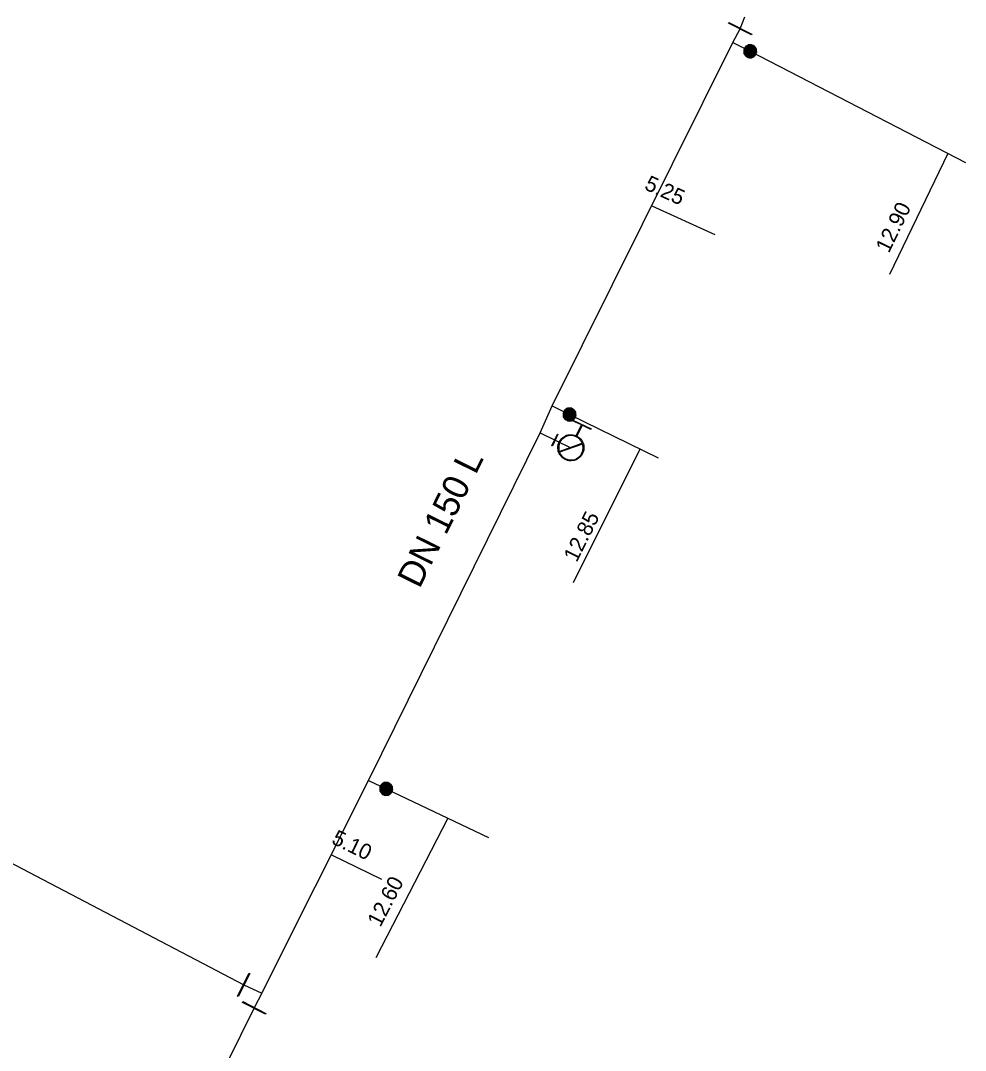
# Model space of a CAD drawing. Extents: x -820257 to -819974, y -1070894 to -1070484.
# Drawn here: x -820109.2 to -820036.2, y -1070745.2 to -1070665.6 of the extents above; entities that cross this region are included whole.
import ezdxf

# ---------------------------------------------------------------- set-up
doc = ezdxf.new("R2010")
doc.units = 0
for name, color, linetype in [('Hyd-odbočka', 7, 'Continuous'), ('Hyd-šoupě', 7, 'Continuous'), ('Hydrant', 7, 'Continuous'), ('Oměrka vodovodu', 7, 'Continuous'), ('Oměrka-text', 7, 'Continuous'), ('Přípojka vodovodu', 7, 'Continuous'), ('Přípojkový uzávěr', 7, 'Continuous'), ('Roz-řad', 7, 'Continuous'), ('Roz-řad-popis základní', 7, 'Continuous'), ('Řad-šoupě', 7, 'Continuous')]:
    doc.layers.add(name, color=color, linetype=linetype)

msp = doc.modelspace()

# ---------------------------------------------------------------- linework, layer by layer
at = {"layer": 'Hyd-odbočka'}
msp.add_line((-820069.077, -1070697.474), (-820066.695, -1070698.626), dxfattribs=at)
at = {"layer": 'Hyd-šoupě'}
msp.add_lwpolyline([(-820067.693, -1070697.588), (-820068.128, -1070698.488), (-820068.156, -1070698.474), (-820067.721, -1070697.574), (-820067.693, -1070697.588)], dxfattribs=at)
at = {"layer": 'Hydrant'}
for points in [[(-820066.29, -1070697.711), (-820065.885, -1070696.866), (-820066.561, -1070696.541), (-820066.534, -1070696.485), (-820065.125, -1070697.161), (-820065.152, -1070697.218), (-820065.828, -1070696.893), (-820066.234, -1070697.738)], [(-820067.591, -1070698.909), (-820065.819, -1070698.286)], [(-820065.799, -1070698.344), (-820067.572, -1070698.968)]]:
    msp.add_lwpolyline(points, dxfattribs=at)
for points in [[(-820066.234, -1070697.738), (-820066.024, -1070697.847), (-820065.874, -1070698.054), (-820065.715, -1070698.273), (-820065.698, -1070698.548), (-820065.68, -1070698.823), (-820065.793, -1070699.059), (-820065.906, -1070699.293), (-820066.128, -1070699.451), (-820066.35, -1070699.609), (-820066.622, -1070699.624), (-820066.893, -1070699.64), (-820067.128, -1070699.528), (-820067.362, -1070699.415), (-820067.52, -1070699.193), (-820067.677, -1070698.971), (-820067.693, -1070698.699), (-820067.709, -1070698.428), (-820067.596, -1070698.193), (-820067.483, -1070697.957), (-820067.258, -1070697.799), (-820067.032, -1070697.641), (-820066.762, -1070697.628), (-820066.508, -1070697.615), (-820066.29, -1070697.711)], [(-820065.819, -1070698.286), (-820065.86, -1070698.182), (-820065.926, -1070698.09), (-820066.076, -1070697.883), (-820066.289, -1070697.781), (-820066.502, -1070697.679), (-820066.757, -1070697.691), (-820067.012, -1070697.703), (-820067.223, -1070697.851), (-820067.434, -1070697.999), (-820067.54, -1070698.22), (-820067.646, -1070698.44), (-820067.629, -1070698.695), (-820067.624, -1070698.806), (-820067.591, -1070698.909)], [(-820067.572, -1070698.968), (-820067.533, -1070699.067), (-820067.467, -1070699.157), (-820067.321, -1070699.366), (-820067.101, -1070699.471), (-820066.881, -1070699.577), (-820066.625, -1070699.562), (-820066.37, -1070699.547), (-820066.163, -1070699.399), (-820065.955, -1070699.252), (-820065.85, -1070699.032), (-820065.743, -1070698.81), (-820065.76, -1070698.553), (-820065.768, -1070698.443), (-820065.799, -1070698.344)]]:
    msp.add_open_spline(points, degree=3, dxfattribs=at)
at = {"layer": 'Oměrka vodovodu'}
for p, q in [((-820037.577, -1070675.914), (-820042.09, -1070685.243)), ((-820060.456, -1070679.934), (-820055.57, -1070682.157)), ((-820061.365, -1070698.725), (-820066.528, -1070709.053)), ((-820076.192, -1070727.239), (-820081.747, -1070738.009)), ((-820085.19, -1070730.062), (-820081.33, -1070731.931))]:
    msp.add_line(p, q, dxfattribs=at)
at = {"layer": 'Přípojka vodovodu'}
for points in [[(-820054.182, -1070667.321), (-820052.85, -1070668.01), (-820036.232, -1070676.61)], [(-820068.149, -1070695.401), (-820066.802, -1070696.061), (-820059.956, -1070699.415)], [(-820082.313, -1070724.324), (-820080.959, -1070724.969), (-820073.047, -1070728.737)]]:
    msp.add_lwpolyline(points, dxfattribs=at)
at = {"layer": 'Přípojkový uzávěr'}
for points in [[(-820052.621, -1070667.565), (-820052.509, -1070667.623), (-820052.432, -1070667.736), (-820052.356, -1070667.848), (-820052.351, -1070667.986), (-820052.346, -1070668.124), (-820052.406, -1070668.24), (-820052.466, -1070668.355), (-820052.579, -1070668.431), (-820052.692, -1070668.506), (-820052.828, -1070668.51), (-820052.965, -1070668.513), (-820053.08, -1070668.454), (-820053.195, -1070668.394), (-820053.271, -1070668.281), (-820053.346, -1070668.168), (-820053.35, -1070668.032), (-820053.354, -1070667.896), (-820053.294, -1070667.78), (-820053.234, -1070667.664), (-820053.119, -1070667.588), (-820053.004, -1070667.512), (-820052.869, -1070667.51), (-820052.733, -1070667.507), (-820052.621, -1070667.565)], [(-820052.642, -1070667.607), (-820052.744, -1070667.555), (-820052.867, -1070667.557), (-820052.99, -1070667.559), (-820053.094, -1070667.628), (-820053.198, -1070667.697), (-820053.253, -1070667.802), (-820053.307, -1070667.906), (-820053.303, -1070668.029), (-820053.3, -1070668.152), (-820053.231, -1070668.255), (-820053.163, -1070668.358), (-820053.059, -1070668.412), (-820052.954, -1070668.466), (-820052.83, -1070668.463), (-820052.707, -1070668.459), (-820052.604, -1070668.391), (-820052.502, -1070668.323), (-820052.448, -1070668.218), (-820052.393, -1070668.113), (-820052.398, -1070667.988), (-820052.402, -1070667.863), (-820052.472, -1070667.761), (-820052.541, -1070667.66), (-820052.642, -1070667.607)], [(-820052.658, -1070667.637), (-820052.564, -1070667.686), (-820052.5, -1070667.78), (-820052.436, -1070667.874), (-820052.432, -1070667.989), (-820052.428, -1070668.105), (-820052.478, -1070668.203), (-820052.528, -1070668.299), (-820052.623, -1070668.363), (-820052.717, -1070668.426), (-820052.832, -1070668.429), (-820052.946, -1070668.432), (-820053.043, -1070668.382), (-820053.139, -1070668.332), (-820053.203, -1070668.237), (-820053.266, -1070668.142), (-820053.269, -1070668.028), (-820053.272, -1070667.914), (-820053.222, -1070667.818), (-820053.172, -1070667.72), (-820053.076, -1070667.656), (-820052.98, -1070667.593), (-820052.866, -1070667.591), (-820052.752, -1070667.589), (-820052.658, -1070667.637)], [(-820052.679, -1070667.676), (-820052.817, -1070667.604), (-820052.965, -1070667.652), (-820053.112, -1070667.699), (-820053.183, -1070667.838), (-820053.255, -1070667.976), (-820053.208, -1070668.124), (-820053.16, -1070668.271), (-820053.023, -1070668.342), (-820052.885, -1070668.414), (-820052.737, -1070668.367), (-820052.589, -1070668.32), (-820052.517, -1070668.183), (-820052.446, -1070668.044), (-820052.492, -1070667.896), (-820052.539, -1070667.749), (-820052.679, -1070667.676)], [(-820052.7, -1070667.717), (-820052.578, -1070667.78), (-820052.537, -1070667.909), (-820052.497, -1070668.038), (-820052.559, -1070668.159), (-820052.622, -1070668.28), (-820052.751, -1070668.321), (-820052.88, -1070668.362), (-820053.001, -1070668.3), (-820053.123, -1070668.237), (-820053.164, -1070668.108), (-820053.205, -1070667.979), (-820053.142, -1070667.858), (-820053.079, -1070667.737), (-820052.95, -1070667.695), (-820052.821, -1070667.654), (-820052.7, -1070667.717)], [(-820052.718, -1070667.752), (-820052.825, -1070667.697), (-820052.938, -1070667.733), (-820053.052, -1070667.77), (-820053.107, -1070667.876), (-820053.162, -1070667.982), (-820053.126, -1070668.096), (-820053.09, -1070668.21), (-820052.983, -1070668.265), (-820052.877, -1070668.32), (-820052.763, -1070668.283), (-820052.649, -1070668.247), (-820052.594, -1070668.141), (-820052.539, -1070668.035), (-820052.575, -1070667.921), (-820052.611, -1070667.808), (-820052.718, -1070667.752)], [(-820052.736, -1070667.787), (-820052.642, -1070667.836), (-820052.611, -1070667.934), (-820052.581, -1070668.033), (-820052.628, -1070668.125), (-820052.676, -1070668.217), (-820052.775, -1070668.248), (-820052.873, -1070668.279), (-820052.965, -1070668.232), (-820053.057, -1070668.184), (-820053.088, -1070668.086), (-820053.12, -1070667.987), (-820053.072, -1070667.895), (-820053.025, -1070667.803), (-820052.927, -1070667.771), (-820052.828, -1070667.739), (-820052.736, -1070667.787)], [(-820052.757, -1070667.829), (-820052.832, -1070667.79), (-820052.912, -1070667.815), (-820052.992, -1070667.841), (-820053.031, -1070667.916), (-820053.07, -1070667.991), (-820053.044, -1070668.071), (-820053.019, -1070668.151), (-820052.944, -1070668.189), (-820052.869, -1070668.228), (-820052.789, -1070668.203), (-820052.709, -1070668.177), (-820052.67, -1070668.102), (-820052.631, -1070668.027), (-820052.657, -1070667.947), (-820052.682, -1070667.868), (-820052.757, -1070667.829)], [(-820052.773, -1070667.859), (-820052.71, -1070667.892), (-820052.689, -1070667.958), (-820052.668, -1070668.024), (-820052.701, -1070668.087), (-820052.733, -1070668.149), (-820052.799, -1070668.17), (-820052.866, -1070668.191), (-820052.928, -1070668.159), (-820052.99, -1070668.126), (-820053.011, -1070668.06), (-820053.032, -1070667.994), (-820053, -1070667.932), (-820052.968, -1070667.869), (-820052.902, -1070667.848), (-820052.835, -1070667.827), (-820052.773, -1070667.859)], [(-820052.793, -1070667.898), (-820052.839, -1070667.875), (-820052.888, -1070667.891), (-820052.937, -1070667.906), (-820052.961, -1070667.952), (-820052.985, -1070667.998), (-820052.969, -1070668.048), (-820052.954, -1070668.097), (-820052.908, -1070668.121), (-820052.862, -1070668.145), (-820052.812, -1070668.129), (-820052.763, -1070668.113), (-820052.739, -1070668.067), (-820052.715, -1070668.021), (-820052.731, -1070667.972), (-820052.746, -1070667.923), (-820052.793, -1070667.898)], [(-820052.815, -1070667.94), (-820052.785, -1070667.955), (-820052.776, -1070667.986), (-820052.766, -1070668.016), (-820052.781, -1070668.045), (-820052.796, -1070668.074), (-820052.826, -1070668.084), (-820052.857, -1070668.094), (-820052.886, -1070668.079), (-820052.915, -1070668.064), (-820052.925, -1070668.033), (-820052.935, -1070668.002), (-820052.92, -1070667.974), (-820052.905, -1070667.944), (-820052.874, -1070667.935), (-820052.843, -1070667.925), (-820052.815, -1070667.94)], [(-820052.829, -1070667.968), (-820052.846, -1070667.959), (-820052.865, -1070667.965), (-820052.883, -1070667.97), (-820052.892, -1070667.988), (-820052.901, -1070668.005), (-820052.895, -1070668.024), (-820052.889, -1070668.042), (-820052.872, -1070668.051), (-820052.854, -1070668.06), (-820052.836, -1070668.054), (-820052.818, -1070668.048), (-820052.809, -1070668.031), (-820052.8, -1070668.013), (-820052.805, -1070667.995), (-820052.811, -1070667.977), (-820052.829, -1070667.968)], [(-820066.582, -1070695.612), (-820066.469, -1070695.667), (-820066.39, -1070695.778), (-820066.311, -1070695.888), (-820066.303, -1070696.026), (-820066.296, -1070696.164), (-820066.353, -1070696.281), (-820066.41, -1070696.398), (-820066.522, -1070696.476), (-820066.633, -1070696.554), (-820066.769, -1070696.56), (-820066.905, -1070696.567), (-820067.022, -1070696.51), (-820067.139, -1070696.453), (-820067.217, -1070696.341), (-820067.295, -1070696.23), (-820067.301, -1070696.094), (-820067.308, -1070695.958), (-820067.251, -1070695.841), (-820067.194, -1070695.724), (-820067.08, -1070695.645), (-820066.967, -1070695.567), (-820066.832, -1070695.561), (-820066.696, -1070695.556), (-820066.582, -1070695.612)], [(-820066.603, -1070695.654), (-820066.706, -1070695.604), (-820066.829, -1070695.608), (-820066.952, -1070695.613), (-820067.054, -1070695.684), (-820067.157, -1070695.756), (-820067.209, -1070695.862), (-820067.261, -1070695.968), (-820067.255, -1070696.091), (-820067.249, -1070696.214), (-820067.178, -1070696.315), (-820067.107, -1070696.416), (-820067.002, -1070696.468), (-820066.896, -1070696.52), (-820066.772, -1070696.514), (-820066.649, -1070696.507), (-820066.548, -1070696.437), (-820066.447, -1070696.366), (-820066.395, -1070696.261), (-820066.343, -1070696.154), (-820066.35, -1070696.029), (-820066.358, -1070695.904), (-820066.429, -1070695.804), (-820066.5, -1070695.704), (-820066.603, -1070695.654)], [(-820066.618, -1070695.685), (-820066.523, -1070695.731), (-820066.457, -1070695.824), (-820066.391, -1070695.916), (-820066.384, -1070696.032), (-820066.378, -1070696.147), (-820066.426, -1070696.246), (-820066.474, -1070696.344), (-820066.567, -1070696.409), (-820066.66, -1070696.474), (-820066.774, -1070696.48), (-820066.889, -1070696.485), (-820066.987, -1070696.437), (-820067.084, -1070696.389), (-820067.15, -1070696.296), (-820067.215, -1070696.202), (-820067.221, -1070696.088), (-820067.226, -1070695.975), (-820067.178, -1070695.877), (-820067.13, -1070695.778), (-820067.035, -1070695.713), (-820066.941, -1070695.647), (-820066.827, -1070695.642), (-820066.713, -1070695.638), (-820066.618, -1070695.685)], [(-820066.638, -1070695.724), (-820066.778, -1070695.655), (-820066.924, -1070695.706), (-820067.07, -1070695.757), (-820067.139, -1070695.896), (-820067.207, -1070696.036), (-820067.157, -1070696.183), (-820067.106, -1070696.329), (-820066.968, -1070696.397), (-820066.828, -1070696.466), (-820066.681, -1070696.416), (-820066.534, -1070696.366), (-820066.465, -1070696.226), (-820066.397, -1070696.087), (-820066.447, -1070695.94), (-820066.496, -1070695.793), (-820066.638, -1070695.724)], [(-820066.658, -1070695.765), (-820066.535, -1070695.825), (-820066.491, -1070695.954), (-820066.448, -1070696.082), (-820066.508, -1070696.204), (-820066.568, -1070696.326), (-820066.696, -1070696.37), (-820066.824, -1070696.414), (-820066.947, -1070696.354), (-820067.07, -1070696.294), (-820067.113, -1070696.166), (-820067.157, -1070696.038), (-820067.097, -1070695.915), (-820067.037, -1070695.793), (-820066.909, -1070695.749), (-820066.781, -1070695.705), (-820066.658, -1070695.765)], [(-820066.675, -1070695.801), (-820066.783, -1070695.748), (-820066.896, -1070695.786), (-820067.009, -1070695.825), (-820067.062, -1070695.933), (-820067.114, -1070696.04), (-820067.076, -1070696.153), (-820067.037, -1070696.266), (-820066.929, -1070696.319), (-820066.822, -1070696.371), (-820066.709, -1070696.333), (-820066.596, -1070696.294), (-820066.543, -1070696.187), (-820066.491, -1070696.079), (-820066.529, -1070695.966), (-820066.567, -1070695.854), (-820066.675, -1070695.801)], [(-820066.692, -1070695.836), (-820066.598, -1070695.882), (-820066.565, -1070695.98), (-820066.532, -1070696.078), (-820066.578, -1070696.171), (-820066.623, -1070696.264), (-820066.721, -1070696.298), (-820066.819, -1070696.331), (-820066.912, -1070696.285), (-820067.005, -1070696.24), (-820067.039, -1070696.142), (-820067.072, -1070696.044), (-820067.027, -1070695.951), (-820066.981, -1070695.858), (-820066.884, -1070695.824), (-820066.786, -1070695.79), (-820066.692, -1070695.836)], [(-820066.713, -1070695.878), (-820066.789, -1070695.841), (-820066.868, -1070695.868), (-820066.947, -1070695.895), (-820066.985, -1070695.971), (-820067.022, -1070696.047), (-820066.995, -1070696.126), (-820066.967, -1070696.206), (-820066.892, -1070696.243), (-820066.816, -1070696.28), (-820066.737, -1070696.253), (-820066.657, -1070696.226), (-820066.62, -1070696.15), (-820066.583, -1070696.074), (-820066.61, -1070695.994), (-820066.637, -1070695.915), (-820066.713, -1070695.878)], [(-820066.728, -1070695.909), (-820066.665, -1070695.94), (-820066.643, -1070696.006), (-820066.62, -1070696.071), (-820066.651, -1070696.134), (-820066.682, -1070696.198), (-820066.748, -1070696.22), (-820066.814, -1070696.242), (-820066.876, -1070696.212), (-820066.939, -1070696.181), (-820066.962, -1070696.115), (-820066.984, -1070696.049), (-820066.954, -1070695.986), (-820066.923, -1070695.923), (-820066.857, -1070695.901), (-820066.791, -1070695.878), (-820066.728, -1070695.909)], [(-820066.747, -1070695.949), (-820066.794, -1070695.926), (-820066.843, -1070695.943), (-820066.891, -1070695.96), (-820066.914, -1070696.006), (-820066.937, -1070696.052), (-820066.92, -1070696.101), (-820066.903, -1070696.15), (-820066.857, -1070696.173), (-820066.811, -1070696.196), (-820066.762, -1070696.179), (-820066.713, -1070696.162), (-820066.69, -1070696.116), (-820066.667, -1070696.069), (-820066.684, -1070696.021), (-820066.7, -1070695.972), (-820066.747, -1070695.949)], [(-820066.768, -1070695.991), (-820066.738, -1070696.005), (-820066.728, -1070696.035), (-820066.718, -1070696.065), (-820066.732, -1070696.095), (-820066.746, -1070696.124), (-820066.777, -1070696.135), (-820066.807, -1070696.146), (-820066.837, -1070696.131), (-820066.866, -1070696.117), (-820066.876, -1070696.086), (-820066.887, -1070696.055), (-820066.873, -1070696.026), (-820066.858, -1070695.997), (-820066.828, -1070695.986), (-820066.797, -1070695.976), (-820066.768, -1070695.991)], [(-820066.782, -1070696.019), (-820066.799, -1070696.01), (-820066.818, -1070696.016), (-820066.836, -1070696.022), (-820066.845, -1070696.04), (-820066.853, -1070696.058), (-820066.847, -1070696.076), (-820066.841, -1070696.094), (-820066.823, -1070696.103), (-820066.805, -1070696.112), (-820066.787, -1070696.105), (-820066.769, -1070696.099), (-820066.76, -1070696.081), (-820066.752, -1070696.063), (-820066.758, -1070696.045), (-820066.764, -1070696.027), (-820066.782, -1070696.019)], [(-820080.745, -1070724.518), (-820080.631, -1070724.572), (-820080.551, -1070724.682), (-820080.471, -1070724.791), (-820080.461, -1070724.929), (-820080.452, -1070725.067), (-820080.508, -1070725.185), (-820080.564, -1070725.302), (-820080.675, -1070725.381), (-820080.786, -1070725.46), (-820080.921, -1070725.469), (-820081.057, -1070725.477), (-820081.175, -1070725.421), (-820081.292, -1070725.365), (-820081.371, -1070725.254), (-820081.45, -1070725.144), (-820081.459, -1070725.008), (-820081.467, -1070724.872), (-820081.411, -1070724.755), (-820081.355, -1070724.637), (-820081.243, -1070724.557), (-820081.13, -1070724.477), (-820080.995, -1070724.47), (-820080.859, -1070724.464), (-820080.745, -1070724.518)], [(-820080.765, -1070724.56), (-820080.868, -1070724.511), (-820080.991, -1070724.517), (-820081.114, -1070724.523), (-820081.216, -1070724.596), (-820081.318, -1070724.668), (-820081.369, -1070724.775), (-820081.419, -1070724.881), (-820081.412, -1070725.004), (-820081.405, -1070725.127), (-820081.333, -1070725.228), (-820081.261, -1070725.328), (-820081.155, -1070725.378), (-820081.048, -1070725.429), (-820080.925, -1070725.422), (-820080.801, -1070725.414), (-820080.701, -1070725.343), (-820080.601, -1070725.271), (-820080.551, -1070725.165), (-820080.5, -1070725.058), (-820080.508, -1070724.933), (-820080.517, -1070724.808), (-820080.589, -1070724.709), (-820080.662, -1070724.609), (-820080.765, -1070724.56)], [(-820080.78, -1070724.591), (-820080.684, -1070724.637), (-820080.617, -1070724.728), (-820080.55, -1070724.82), (-820080.542, -1070724.935), (-820080.534, -1070725.051), (-820080.582, -1070725.15), (-820080.628, -1070725.248), (-820080.721, -1070725.315), (-820080.813, -1070725.381), (-820080.927, -1070725.388), (-820081.041, -1070725.395), (-820081.14, -1070725.348), (-820081.238, -1070725.301), (-820081.305, -1070725.208), (-820081.371, -1070725.115), (-820081.378, -1070725.002), (-820081.385, -1070724.888), (-820081.338, -1070724.79), (-820081.291, -1070724.691), (-820081.197, -1070724.624), (-820081.103, -1070724.557), (-820080.989, -1070724.551), (-820080.875, -1070724.546), (-820080.78, -1070724.591)], [(-820080.799, -1070724.631), (-820080.94, -1070724.563), (-820081.086, -1070724.616), (-820081.231, -1070724.668), (-820081.298, -1070724.809), (-820081.365, -1070724.949), (-820081.313, -1070725.095), (-820081.261, -1070725.241), (-820081.122, -1070725.308), (-820080.981, -1070725.375), (-820080.834, -1070725.323), (-820080.688, -1070725.271), (-820080.621, -1070725.131), (-820080.554, -1070724.991), (-820080.606, -1070724.845), (-820080.657, -1070724.698), (-820080.799, -1070724.631)], [(-820080.819, -1070724.672), (-820080.695, -1070724.731), (-820080.65, -1070724.859), (-820080.605, -1070724.986), (-820080.664, -1070725.109), (-820080.722, -1070725.232), (-820080.85, -1070725.278), (-820080.978, -1070725.323), (-820081.101, -1070725.265), (-820081.225, -1070725.206), (-820081.27, -1070725.078), (-820081.315, -1070724.95), (-820081.256, -1070724.827), (-820081.198, -1070724.704), (-820081.07, -1070724.659), (-820080.942, -1070724.613), (-820080.819, -1070724.672)], [(-820080.836, -1070724.708), (-820080.944, -1070724.656), (-820081.057, -1070724.696), (-820081.169, -1070724.736), (-820081.221, -1070724.844), (-820081.272, -1070724.952), (-820081.232, -1070725.065), (-820081.193, -1070725.177), (-820081.084, -1070725.229), (-820080.976, -1070725.28), (-820080.864, -1070725.24), (-820080.751, -1070725.2), (-820080.7, -1070725.092), (-820080.648, -1070724.984), (-820080.688, -1070724.872), (-820080.727, -1070724.76), (-820080.836, -1070724.708)], [(-820080.853, -1070724.744), (-820080.758, -1070724.789), (-820080.724, -1070724.886), (-820080.689, -1070724.984), (-820080.734, -1070725.078), (-820080.779, -1070725.171), (-820080.876, -1070725.205), (-820080.974, -1070725.24), (-820081.068, -1070725.195), (-820081.161, -1070725.151), (-820081.195, -1070725.053), (-820081.23, -1070724.956), (-820081.186, -1070724.863), (-820081.141, -1070724.769), (-820081.044, -1070724.734), (-820080.947, -1070724.699), (-820080.853, -1070724.744)], [(-820080.872, -1070724.786), (-820080.949, -1070724.749), (-820081.028, -1070724.777), (-820081.107, -1070724.805), (-820081.143, -1070724.882), (-820081.18, -1070724.958), (-820081.151, -1070725.037), (-820081.123, -1070725.116), (-820081.047, -1070725.152), (-820080.971, -1070725.188), (-820080.892, -1070725.16), (-820080.813, -1070725.133), (-820080.776, -1070725.056), (-820080.74, -1070724.98), (-820080.768, -1070724.901), (-820080.796, -1070724.822), (-820080.872, -1070724.786)], [(-820080.887, -1070724.817), (-820080.824, -1070724.847), (-820080.801, -1070724.912), (-820080.778, -1070724.978), (-820080.808, -1070725.041), (-820080.838, -1070725.105), (-820080.904, -1070725.128), (-820080.969, -1070725.151), (-820081.032, -1070725.121), (-820081.096, -1070725.091), (-820081.119, -1070725.025), (-820081.142, -1070724.96), (-820081.112, -1070724.896), (-820081.082, -1070724.833), (-820081.016, -1070724.81), (-820080.951, -1070724.787), (-820080.887, -1070724.817)], [(-820080.906, -1070724.857), (-820080.953, -1070724.834), (-820081.002, -1070724.852), (-820081.05, -1070724.869), (-820081.072, -1070724.916), (-820081.095, -1070724.963), (-820081.077, -1070725.011), (-820081.06, -1070725.06), (-820081.014, -1070725.082), (-820080.967, -1070725.105), (-820080.918, -1070725.087), (-820080.869, -1070725.07), (-820080.847, -1070725.023), (-820080.824, -1070724.977), (-820080.842, -1070724.928), (-820080.859, -1070724.879), (-820080.906, -1070724.857)], [(-820080.926, -1070724.899), (-820080.896, -1070724.913), (-820080.886, -1070724.943), (-820080.875, -1070724.973), (-820080.889, -1070725.003), (-820080.903, -1070725.032), (-820080.934, -1070725.043), (-820080.964, -1070725.054), (-820080.994, -1070725.04), (-820081.023, -1070725.026), (-820081.034, -1070724.995), (-820081.044, -1070724.965), (-820081.031, -1070724.936), (-820081.016, -1070724.906), (-820080.986, -1070724.895), (-820080.956, -1070724.885), (-820080.926, -1070724.899)], [(-820080.94, -1070724.927), (-820080.958, -1070724.919), (-820080.976, -1070724.925), (-820080.994, -1070724.931), (-820081.002, -1070724.949), (-820081.011, -1070724.967), (-820081.004, -1070724.985), (-820080.998, -1070725.003), (-820080.98, -1070725.012), (-820080.962, -1070725.02), (-820080.944, -1070725.014), (-820080.926, -1070725.007), (-820080.918, -1070724.99), (-820080.909, -1070724.971), (-820080.915, -1070724.954), (-820080.922, -1070724.936), (-820080.94, -1070724.927)]]:
    msp.add_open_spline(points, degree=3, dxfattribs=at)
at = {"layer": 'Roz-řad'}
for p, q in [((-820053.629, -1070666.271), (-820053.253, -1070665.35)), ((-820091.962, -1070740.107), (-820090.554, -1070740.758)), ((-820090.554, -1070740.758), (-820091.157, -1070741.885))]:
    msp.add_line(p, q, dxfattribs=at)
for points in [[(-820069.077, -1070697.474), (-820068.149, -1070695.401), (-820054.182, -1070667.321), (-820053.629, -1070666.271)], [(-820090.554, -1070740.758), (-820082.313, -1070724.324), (-820069.077, -1070697.474)], [(-820144.508, -1070712.712), (-820124.791, -1070722.905), (-820124.049, -1070723.282), (-820091.962, -1070740.107)], [(-820091.157, -1070741.885), (-820096.482, -1070752.661), (-820104.571, -1070768.915)]]:
    msp.add_lwpolyline(points, dxfattribs=at)
at = {"layer": 'Řad-šoupě'}
for points in [[(-820054.504, -1070665.787), (-820052.724, -1070666.697), (-820052.752, -1070666.753), (-820054.533, -1070665.842), (-820054.504, -1070665.787)], [(-820092.444, -1070740.982), (-820091.534, -1070739.202), (-820091.478, -1070739.23), (-820092.389, -1070741.011), (-820092.444, -1070740.982)], [(-820092.032, -1070741.401), (-820090.252, -1070742.311), (-820090.28, -1070742.367), (-820092.061, -1070741.456), (-820092.032, -1070741.401)]]:
    msp.add_lwpolyline(points, dxfattribs=at)

# ---------------------------------------------------------------- texts
at = {"layer": 'Oměrka-text'}
for s, rotation, p in [(' 5.25', 335.53572, (-820061.501, -1070678.457)), ('12.90', 64.18416, (-820042.143, -1070683.656)), ('12.85', 63.43938, (-820066.249, -1070707.532)), (' 5.10', 334.16388, (-820085.655, -1070728.966)), ('12.60', 62.71602, (-820081.41, -1070735.706))]:
    msp.add_text(s, height=1.2, rotation=rotation, dxfattribs=at).set_placement(p)
at = {"layer": 'Roz-řad-popis základní'}
msp.add_text('DN 150 L', height=2, rotation=63.75851, dxfattribs=at).set_placement((-820078.386, -1070709.572))

doc.saveas('drawing.dxf')
